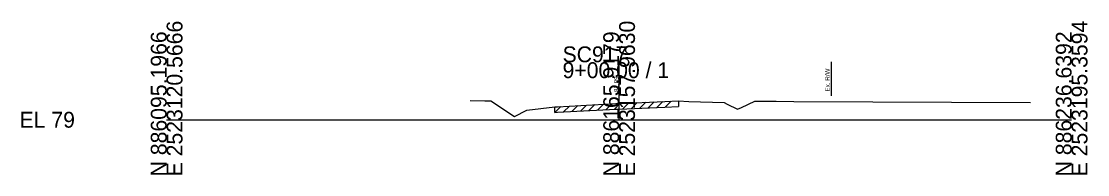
# Model space of a CAD drawing. Extents: x -26 to 218, y -10 to 12021.
# Drawn here: x -25.7 to 162.8, y 8490.3 to 8517.4 of the extents above; entities that cross this region are included whole.
import ezdxf

# ---------------------------------------------------------------- set-up
doc = ezdxf.new("R2010")
doc.units = 0
for name, color, linetype in [('RD_GPK_XS_Cell', 7, 'Continuous'), ('RD_XS_ExGround', 7, 'Continuous'), ('RD_XS_ExPaveRet', 7, 'Continuous'), ('RD_XS_ExRW', 7, 'Continuous'), ('RD_XS_TX_Elev_EX', 7, 'Continuous')]:
    doc.layers.add(name, color=color, linetype=linetype)

msp = doc.modelspace()

# ---------------------------------------------------------------- linework, layer by layer
at = {"layer": 'RD_GPK_XS_Cell'}
for p, q in [((80, 8500), (80, 8510.15)), ((0, 8500), (80, 8500)), ((80, 8500), (160, 8500))]:
    msp.add_line(p, q, dxfattribs=at)
at = {"layer": 'RD_XS_ExGround'}
for p, q in [((53.66, 8503.38), (56.24, 8503.34)), ((56.24, 8503.34), (57.33, 8503.33)), ((57.33, 8503.33), (61.5, 8500.59)), ((69.1, 8502.31), (79.4, 8502.87)), ((79.4, 8502.87), (80, 8502.89)), ((80, 8502.89), (88.07, 8503.23)), ((88.07, 8503.23), (90.52, 8503.32)), ((90.52, 8503.32), (92.32, 8503.25)), ((92.32, 8503.25), (98.57, 8503.05)), ((98.57, 8503.05), (99.11, 8502.77)), ((101.61, 8502.17), (103.97, 8503.27)), ((103.97, 8503.27), (107.77, 8503.27)), ((107.77, 8503.27), (110.86, 8503.24)), ((110.86, 8503.24), (152.73, 8503.03)), ((61.5, 8500.59), (63.7, 8501.67)), ((63.7, 8501.67), (68.66, 8502.29)), ((68.66, 8502.29), (69.1, 8502.31)), ((99.11, 8502.77), (100.91, 8501.85)), ((100.91, 8501.85), (101.61, 8502.17))]:
    msp.add_line(p, q, dxfattribs=at)
at = {"layer": 'RD_XS_ExPaveRet'}
for p, q in [((77.66, 8501.77), (78.72, 8502.83)), ((79.16, 8501.85), (80.21, 8502.9)), ((80.66, 8501.92), (81.7, 8502.96)), ((82.16, 8501.98), (83.2, 8503.02)), ((83.66, 8502.04), (84.7, 8503.09)), ((85.16, 8502.11), (86.2, 8503.15)), ((86.66, 8502.17), (87.7, 8503.21)), ((88.16, 8502.23), (89.2, 8503.27)), ((90.52, 8503.32), (90.52, 8502.32)), ((68.66, 8501.29), (69.72, 8502.34)), ((68.66, 8501.29), (68.66, 8502.29)), ((68.66, 8501.29), (69.1, 8501.31)), ((69.1, 8501.31), (79.4, 8501.87)), ((70.16, 8501.37), (71.22, 8502.42)), ((71.66, 8501.45), (72.72, 8502.5)), ((73.16, 8501.53), (74.22, 8502.59)), ((74.66, 8501.61), (75.72, 8502.67)), ((76.16, 8501.69), (77.22, 8502.75)), ((79.4, 8501.87), (80, 8501.89)), ((80, 8501.89), (88.07, 8502.23)), ((88.07, 8502.23), (90.52, 8502.32))]:
    msp.add_line(p, q, dxfattribs=at)
at = {"layer": 'RD_XS_ExRW'}
msp.add_line((117.5, 8510.2), (117.5, 8504.2), dxfattribs=at)
msp.add_line((117.5, 8510.2), (117.5, 8504.2), dxfattribs=at)

# ---------------------------------------------------------------- texts
at = {"layer": 'RD_GPK_XS_Cell'}
for s, p in [('E 2523120.5666', (2.8, 8490)), ('E 2523157.9630', (82.8, 8490)), ('E 2523195.3594', (162.8, 8490)), ('N 886095.1966', (0, 8490)), ('N 886165.9179', (80, 8490)), ('N 886236.6392', (160, 8490))]:
    msp.add_text(s, height=2.8, rotation=90, dxfattribs=at).set_placement(p)
for s, p in [('SC917', (70, 8510.15)), ('9+00.00 / 1', (70, 8507.35)), ('EL 79', (-26, 8498.6))]:
    msp.add_text(s, height=2.8, dxfattribs=at).set_placement(p)
at = {"layer": 'RD_XS_ExRW'}
msp.add_text('Ex. R/W ', height=0.8, rotation=90, dxfattribs=at).set_placement((117.25, 8504.99))
msp.add_text('Ex. R/W ', height=0.8, rotation=90, dxfattribs=at).set_placement((117.25, 8504.99))
at = {"layer": 'RD_XS_TX_Elev_EX'}
msp.add_text('81.89', height=0.8, rotation=90, dxfattribs=at).set_placement((79.9, 8504.89))

doc.saveas('drawing.dxf')
